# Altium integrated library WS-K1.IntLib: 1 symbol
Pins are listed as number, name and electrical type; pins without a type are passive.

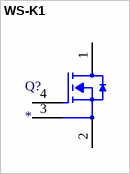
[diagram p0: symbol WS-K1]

## WS-K1
designator Q?
footprint WS-K1 (Wolfspeed K1-package MOSFET)
pins: 1 Drain, 2 Power Source, 3 Driver Source, 4 Gate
